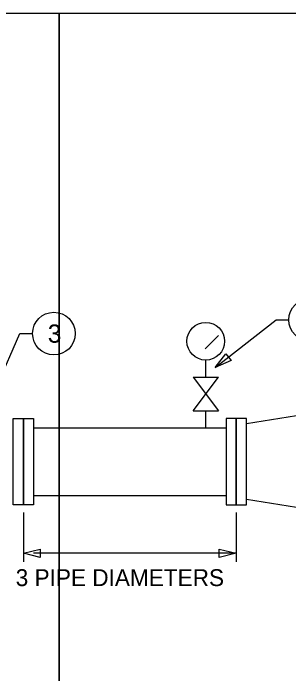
# Model space of a CAD drawing. Extents: x 10291.2 to 10382.2, y 10083.1 to 10135.3.
# Drawn here: x 10334.84 to 10345.72, y 10109.18 to 10135.29 of the extents above; entities that cross this region are included whole.
import ezdxf

# ---------------------------------------------------------------- set-up
doc = ezdxf.new("R2010")
doc.units = 0
for name, color, linetype in [('G-ANNO-NPLT', 7, 'Continuous'), ('G-ANNO-SYMB', 7, 'Continuous'), ('G-DETL-LINE', 7, 'Continuous'), ('G-DETL-TEXT', 7, 'Continuous')]:
    doc.layers.add(name, color=color, linetype=linetype)

msp = doc.modelspace()

# ---------------------------------------------------------------- linework, layer by layer
at = {"layer": 'G-ANNO-NPLT'}
for points in [[(10291.157, 10086.15), (10291.157, 10135.292), (10336.657, 10135.292), (10336.657, 10086.15)], [(10336.657, 10086.15), (10336.657, 10135.292), (10382.157, 10135.292), (10382.157, 10086.15)]]:
    msp.add_lwpolyline(points, close=True, dxfattribs=at)
at = {"layer": 'G-ANNO-SYMB'}
for centre in [(10346.562, 10123.174), (10336.45, 10122.629)]:
    msp.add_circle(centre, 0.843, dxfattribs=at)
at = {"layer": 'G-DETL-LINE'}
for p, q in [((10342.413, 10122.022), (10342.94, 10122.548)), ((10342.443, 10120.908), (10342.443, 10121.583)), ((10341.943, 10120.908), (10342.943, 10120.908)), ((10341.943, 10119.574), (10342.943, 10120.908)), ((10341.943, 10120.908), (10342.943, 10119.574)), ((10341.943, 10119.574), (10342.943, 10119.574)), ((10342.443, 10118.9), (10342.443, 10119.574)), ((10346.364, 10119.436), (10344.045, 10119.066)), ((10335.644, 10118.9), (10343.244, 10118.9)), ((10335.644, 10116.233), (10343.244, 10116.233)), ((10346.364, 10115.696), (10344.045, 10116.066))]:
    msp.add_line(p, q, dxfattribs=at)
for points in [[(10334.843, 10119.269), (10335.244, 10119.269), (10335.244, 10115.864), (10334.843, 10115.864)], [(10335.244, 10119.269), (10335.644, 10119.269), (10335.644, 10115.864), (10335.244, 10115.864)], [(10343.644, 10119.269), (10343.244, 10119.269), (10343.244, 10115.864), (10343.644, 10115.864)], [(10344.045, 10119.269), (10343.644, 10119.269), (10343.644, 10115.864), (10344.045, 10115.864)]]:
    msp.add_lwpolyline(points, close=True, dxfattribs=at)
msp.add_circle((10342.443, 10122.327), 0.744, dxfattribs=at)
at = {"layer": 'G-DETL-TEXT'}
for p, q in [((10342.813, 10121.289), (10345.219, 10123.174)), ((10345.219, 10123.174), (10345.719, 10123.174)), ((10333.644, 10119.305), (10335.107, 10122.629)), ((10335.107, 10122.629), (10335.607, 10122.629)), ((10335.244, 10115.564), (10335.244, 10113.615)), ((10343.644, 10115.564), (10343.644, 10113.615)), ((10343.644, 10113.948), (10335.644, 10113.948))]:
    msp.add_line(p, q, dxfattribs=at)
for points in [[(10343.44, 10121.569), (10342.813, 10121.289), (10343.235, 10121.831)], [(10335.91, 10113.781), (10335.244, 10113.948), (10335.91, 10114.115)], [(10342.978, 10114.115), (10343.644, 10113.948), (10342.978, 10113.781)]]:
    msp.add_lwpolyline(points, close=True, dxfattribs=at)

# ---------------------------------------------------------------- texts
at = {"layer": 'G-ANNO-SYMB'}
msp.add_text('3', height=0.721, dxfattribs=at).set_placement((10336.208, 10122.269))
at = {"layer": 'G-DETL-TEXT'}
msp.add_text('3 PIPE DIAMETERS', height=0.66667, dxfattribs=at).set_placement((10334.941, 10112.65))

doc.saveas('drawing.dxf')
